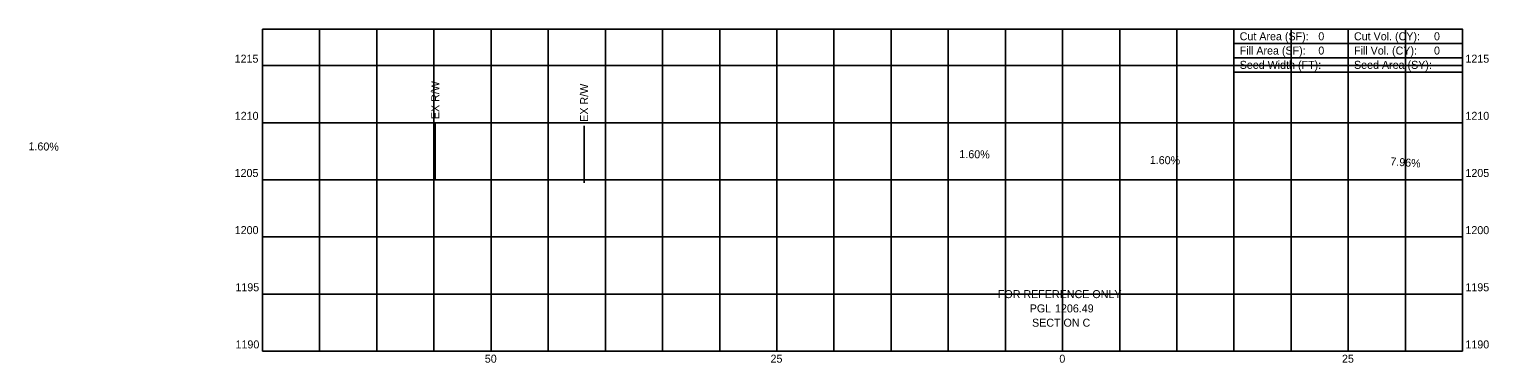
# Model space of a CAD drawing. Extents: x -90 to 37, y 1189 to 1218.
import ezdxf

# ---------------------------------------------------------------- set-up
doc = ezdxf.new("R2010")
doc.units = 0
for name, color, linetype in [('Default', 7, 'Continuous'), ('RS_Raster1', 7, 'Continuous'), ('UT_X_Cable_TV_FO', 7, 'Continuous'), ('UT_X_Gas_Text', 7, 'Continuous'), ('UT_X_Overhead_Combined', 7, 'Continuous'), ('UT_X_Overhead_Telecom', 7, 'Continuous')]:
    doc.layers.add(name, color=color, linetype=linetype)

msp = doc.modelspace()

# ---------------------------------------------------------------- linework, layer by layer
at = {"layer": 'Default'}
msp.add_circle((35, 1218.18), 0.000417, dxfattribs=at)
msp.add_circle((35, 1218.18), 0.000417, dxfattribs=at)
msp.add_circle((35, 1218.18), 0.000417, dxfattribs=at)
msp.add_circle((35, 1218.18), 0.000417, dxfattribs=at)
msp.add_circle((35, 1218.18), 0.000417, dxfattribs=at)
msp.add_circle((35, 1218.18), 0.000417, dxfattribs=at)
msp.add_circle((35, 1218.18), 0.000417, dxfattribs=at)
msp.add_circle((35, 1218.18), 0.000417, dxfattribs=at)
msp.add_circle((35, 1218.18), 0.000417, dxfattribs=at)
msp.add_circle((35, 1218.18), 0.000417, dxfattribs=at)
msp.add_circle((35, 1218.18), 0.000417, dxfattribs=at)
msp.add_circle((35, 1218.18), 0.000417, dxfattribs=at)
at = {"layer": 'RS_Raster1'}
msp.add_lwpolyline([(15, 1218.18), (35, 1218.18), (35, 1214.43), (15, 1214.43)], close=True, dxfattribs=at)
at = {"layer": 'UT_X_Cable_TV_FO'}
for p, q in [((-54.89, 1204.96), (-54.89, 1209.96)), ((-41.86, 1204.73), (-41.86, 1209.73))]:
    msp.add_line(p, q, dxfattribs=at)
at = {"layer": 'UT_X_Gas_Text'}
for p, q in [((15, 1218.18), (35, 1218.18)), ((15, 1218.18), (15, 1215.68)), ((25, 1218.18), (25, 1214.43)), ((35, 1218.18), (35, 1215.68)), ((15, 1216.93), (35, 1216.93)), ((15, 1215.68), (35, 1215.68)), ((23.3, 1215.06), (23.3, 1215.06)), ((32.95, 1215.06), (32.95, 1215.06))]:
    msp.add_line(p, q, dxfattribs=at)
msp.add_lwpolyline([(15, 1215.68), (15, 1214.43), (35, 1214.43), (35, 1215.68)], dxfattribs=at)
at = {"layer": 'UT_X_Overhead_Telecom'}
for p, q in [((-70, 1218.18), (35, 1218.18)), ((-70, 1190), (-70, 1218.18)), ((-65, 1190), (-65, 1218.18)), ((-60, 1190), (-60, 1218.18)), ((-55, 1190), (-55, 1218.18)), ((-50, 1190), (-50, 1218.18)), ((-45, 1190), (-45, 1218.18)), ((-40, 1190), (-40, 1218.18)), ((-35, 1190), (-35, 1218.18)), ((-30, 1190), (-30, 1218.18)), ((-25, 1190), (-25, 1218.18)), ((-20, 1190), (-20, 1218.18)), ((-15, 1190), (-15, 1218.18)), ((-10, 1190), (-10, 1218.18)), ((-5, 1190), (-5, 1218.18)), ((0, 1190), (0, 1218.18)), ((5, 1190), (5, 1218.18)), ((10, 1190), (10, 1218.18)), ((15, 1190), (15, 1218.18)), ((20, 1190), (20, 1218.18)), ((25, 1190), (25, 1218.18)), ((30, 1190), (30, 1218.18)), ((35, 1190), (35, 1218.18)), ((-70, 1215), (35, 1215)), ((-70, 1210), (35, 1210)), ((-70, 1205), (35, 1205)), ((-70, 1200), (35, 1200)), ((-70, 1195), (35, 1195)), ((-70, 1190), (35, 1190))]:
    msp.add_line(p, q, dxfattribs=at)

# ---------------------------------------------------------------- texts
at = {"layer": 'UT_X_Cable_TV_FO'}
for p in [(-54.54, 1210.31), (-41.51, 1210.08)]:
    msp.add_text('EX R/W', height=0.7, rotation=90, dxfattribs=at).set_placement(p)
at = {"layer": 'UT_X_Overhead_Combined'}
for s, p in [('Cut Area (SF):', (15.5, 1217.21)), ('0', (22.38, 1217.21)), ('Cut Vol. (CY):', (25.5, 1217.21)), ('0', (32.5, 1217.21)), ('1215', (-72.44, 1215.25)), ('Fill Area (SF):', (15.5, 1215.96)), ('0', (22.38, 1215.96)), ('Fill Vol. (CY):', (25.5, 1215.96)), ('0', (32.5, 1215.96)), ('1215', (35.25, 1215.25)), ('Seed Width (FT):', (15.5, 1214.71)), ('Seed Area (SY):', (25.5, 1214.71)), ('1210', (-72.43, 1210.25)), ('1210', (35.25, 1210.25)), ('1205', (-72.44, 1205.25)), ('1205', (35.25, 1205.25)), ('1200', (-72.43, 1200.25)), ('1200', (35.25, 1200.25)), ('1195', (-72.37, 1195.25)), ('1195', (35.25, 1195.25)), ('FOR REFERENCE ONLY', (-5.66, 1194.65)), ('PGL ', (-2.87, 1193.4)), ('1206.49', (-0.66, 1193.4)), ('SECTION C', (-2.67, 1192.15)), ('1190', (-72.36, 1190.25)), ('1190', (35.25, 1190.25)), ('50', (-50.55, 1189)), ('25', (-25.55, 1189)), ('0', (-0.28, 1189)), ('25', (24.45, 1189))]:
    msp.add_text(s, height=0.7, dxfattribs=at).set_placement(p)
for s, rotation, p in [('1.60%', 359.0833, (-90.48, 1207.59)), ('1.60%', 359.0833, (-9.03, 1206.91)), ('1.60%', 359.0833, (7.63, 1206.39)), ('7.96%', 355.4516, (28.66, 1206.28))]:
    msp.add_text(s, height=0.7, rotation=rotation, dxfattribs=at).set_placement(p)

doc.saveas('drawing.dxf')
